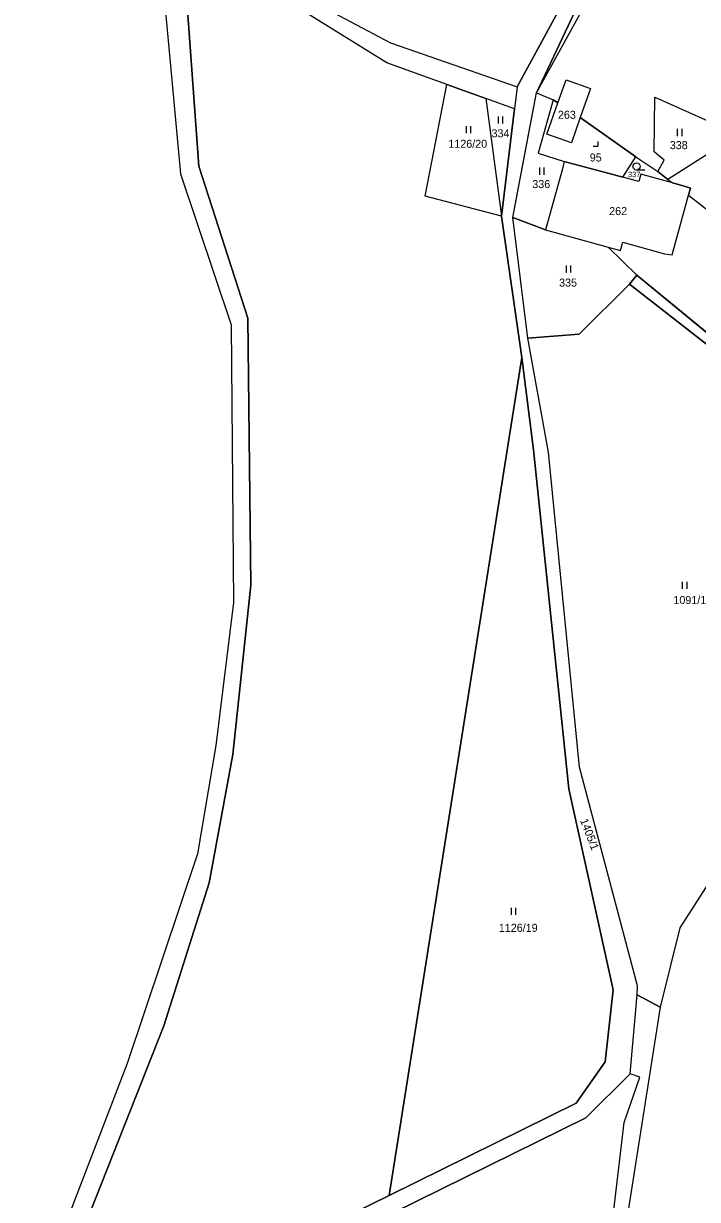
# Model space of a CAD drawing. Extents: x -588699 to -585793, y -1060280 to -1056731.
# Drawn here: x -587669 to -587526.4, y -1058613.5 to -1058364.5 of the extents above; entities that cross this region are included whole.
import ezdxf

# ---------------------------------------------------------------- set-up
doc = ezdxf.new("R2010")
doc.units = 0
for name, color, linetype in [('Druh pozemku', 7, 'Continuous'), ('Lesy', 7, 'Continuous'), ('Parcela nároku', 7, 'Continuous')]:
    doc.layers.add(name, color=color, linetype=linetype)

msp = doc.modelspace()

# ---------------------------------------------------------------- linework, layer by layer
at = {"layer": 'Druh pozemku'}
for p, q in [((-587568.6, -1058384.17), (-587568.6, -1058385.67)), ((-587567.58, -1058385.67), (-587567.58, -1058384.17)), ((-587575.35, -1058386.23), (-587575.35, -1058387.73)), ((-587574.33, -1058387.73), (-587574.33, -1058386.23)), ((-587530.66, -1058386.82), (-587530.66, -1058388.32)), ((-587529.64, -1058388.32), (-587529.64, -1058386.82)), ((-587559.82, -1058395.01), (-587559.82, -1058396.51)), ((-587558.8, -1058396.51), (-587558.8, -1058395.01)), ((-587537.52, -1058395.51), (-587539.27, -1058395.51)), ((-587554.19, -1058415.74), (-587554.19, -1058417.24)), ((-587553.17, -1058417.24), (-587553.17, -1058415.74)), ((-587529.59, -1058482.69), (-587529.59, -1058484.19)), ((-587528.57, -1058484.19), (-587528.57, -1058482.69)), ((-587565.84, -1058551.72), (-587565.84, -1058553.22)), ((-587564.82, -1058553.22), (-587564.82, -1058551.72))]:
    msp.add_line(p, q, dxfattribs=at)
msp.add_lwpolyline([(-587548.43, -1058390.48), (-587547.43, -1058390.48), (-587547.43, -1058389.48)], dxfattribs=at)
msp.add_circle((-587539.27, -1058394.76), 0.75, dxfattribs=at)
at = {"layer": 'Lesy'}
for p, q in [((-587560.48, -1058379.18), (-587539.23, -1058340.65)), ((-587565.45, -1058405.55), (-587560.48, -1058379.18)), ((-587562.32, -1058431.12), (-587565.45, -1058405.55)), ((-587539.18, -1058417.8), (-587540.79, -1058419.7)), ((-587518.94, -1058434.42), (-587539.18, -1058417.8)), ((-587540.79, -1058419.7), (-587551.44, -1058430.25)), ((-587551.44, -1058430.25), (-587562.32, -1058431.12))]:
    msp.add_line(p, q, dxfattribs=at)
at = {"layer": 'Parcela nároku'}
for points in [[(-587737.19, -1058617.25), (-587726.96, -1058577.41), (-587725.51, -1058469.33), (-587723.26, -1058358.68), (-587722.78, -1058330.1), (-587713.89, -1058330.1), (-587711.77, -1058326.33), (-587706.96, -1058322.08), (-587695.94, -1058320.38), (-587639.64, -1058348.59), (-587638.99, -1058362.02), (-587635.81, -1058396.35), (-587625.09, -1058428.31), (-587624.61, -1058487.07), (-587628.3, -1058517.38), (-587632.21, -1058540.26), (-587647.07, -1058584.65), (-587664.66, -1058630.41)], [(-587548.89, -1058349.03), (-587564.56, -1058377.91), (-587565.12, -1058382.56), (-587567.87, -1058405.29), (-587563.56, -1058435.22), (-587561.12, -1058454.74), (-587553.58, -1058526.52), (-587544.23, -1058569.1), (-587545.9, -1058584.35), (-587552.09, -1058593.05), (-587591.67, -1058612.59), (-587607.6, -1058620.46)], [(-587662.12, -1058634.33), (-587639.34, -1058576.72), (-587629.73, -1058546.44), (-587624.7, -1058519.28), (-587620.91, -1058483.41), (-587621.58, -1058426.86), (-587631.96, -1058394.68), (-587634.38, -1058360.7), (-587631.34, -1058352.01), (-587634.55, -1058350.69), (-587638.99, -1058362.02), (-587635.81, -1058396.35), (-587625.09, -1058428.31), (-587624.61, -1058487.07), (-587628.3, -1058517.38), (-587632.21, -1058540.26), (-587647.07, -1058584.65), (-587664.66, -1058630.41)], [(-587607.6, -1058620.46), (-587591.67, -1058612.59), (-587563.56, -1058435.22), (-587567.87, -1058405.29), (-587584.03, -1058401.03), (-587579.42, -1058377.42), (-587592.13, -1058372.84), (-587613.98, -1058359.18), (-587631.34, -1058352.01), (-587634.38, -1058360.7), (-587631.96, -1058394.68), (-587621.58, -1058426.86), (-587620.91, -1058483.41), (-587624.7, -1058519.28), (-587629.73, -1058546.44), (-587639.34, -1058576.72), (-587662.12, -1058634.33)], [(-587614.01, -1058356.52), (-587591.38, -1058368.57), (-587564.56, -1058377.91), (-587565.12, -1058382.56), (-587571.21, -1058380.37), (-587579.42, -1058377.42), (-587592.13, -1058372.84), (-587613.98, -1058359.18)], [(-587605.95, -1058623.77), (-587550, -1058596.19), (-587540.61, -1058586.85), (-587539.12, -1058570.16), (-587539.08, -1058568.25), (-587551.33, -1058521.95), (-587557.89, -1058455.23), (-587562.32, -1058431.12), (-587565.45, -1058405.55), (-587562.72, -1058391.01), (-587560.48, -1058379.18), (-587551.32, -1058359.88)], [(-587551.32, -1058359.88), (-587560.48, -1058379.18), (-587556.95, -1058380.65), (-587555.94, -1058381.31), (-587554.2, -1058376.4), (-587549.02, -1058378.23), (-587551.19, -1058384.39), (-587539.4, -1058392.75), (-587534.78, -1058395.8), (-587533.41, -1058393.41), (-587535.52, -1058391.66), (-587535.42, -1058380.1), (-587517.68, -1058388.02), (-587532.64, -1058397.54), (-587531.66, -1058398.23), (-587529.42, -1058398.84), (-587527.85, -1058399.33), (-587528.28, -1058400.85), (-587508.17, -1058416.49), (-587489.24, -1058400.75), (-587498.12, -1058378.59), (-587502.56, -1058362.06)]]:
    msp.add_lwpolyline(points, dxfattribs=at)
for points in [[(-587575.94, -1058326.51), (-587584.66, -1058324.18), (-587593.29, -1058321.73), (-587594.36, -1058321.43), (-587610.69, -1058335.67), (-587630.7, -1058349.56), (-587614.01, -1058356.52), (-587591.38, -1058368.57), (-587564.56, -1058377.91), (-587548.89, -1058349.03), (-587542.26, -1058338.73), (-587542.96, -1058338.45), (-587556.01, -1058332.97), (-587562.08, -1058330.38), (-587567.25, -1058328.93)], [(-587555.94, -1058381.31), (-587554.2, -1058376.4), (-587549.02, -1058378.23), (-587551.19, -1058384.39), (-587553.07, -1058389.74), (-587558.27, -1058387.9)], [(-587584.03, -1058401.03), (-587579.42, -1058377.42), (-587571.21, -1058380.37), (-587567.87, -1058405.29)], [(-587560.13, -1058391.95), (-587554.61, -1058393.67), (-587554.98, -1058395.27), (-587558.05, -1058406.42), (-587558.54, -1058408.19), (-587565.45, -1058405.55), (-587562.72, -1058391.01), (-587560.48, -1058379.18), (-587556.95, -1058380.65)], [(-587565.12, -1058382.56), (-587571.21, -1058380.37), (-587567.87, -1058405.29)], [(-587556.95, -1058380.65), (-587560.13, -1058391.95), (-587554.61, -1058393.67), (-587542.18, -1058397.01), (-587539.4, -1058392.75), (-587551.19, -1058384.39), (-587553.07, -1058389.74), (-587558.27, -1058387.9), (-587555.94, -1058381.31)], [(-587535.52, -1058391.66), (-587535.42, -1058380.1), (-587517.68, -1058388.02), (-587532.64, -1058397.54), (-587534.78, -1058395.8), (-587533.41, -1058393.41)], [(-587554.98, -1058395.27), (-587558.05, -1058406.42), (-587558.54, -1058408.19), (-587545.3, -1058411.83), (-587542.65, -1058412.55), (-587542.17, -1058410.8), (-587533.38, -1058413.22), (-587531.76, -1058413.48), (-587528.28, -1058400.85), (-587527.85, -1058399.33), (-587529.42, -1058398.84), (-587531.66, -1058398.23), (-587538.37, -1058396.38), (-587538.79, -1058397.92), (-587542.18, -1058397.01), (-587554.61, -1058393.67)], [(-587532.64, -1058397.54), (-587531.66, -1058398.23), (-587538.37, -1058396.38), (-587538.79, -1058397.92), (-587542.18, -1058397.01), (-587539.4, -1058392.75), (-587534.78, -1058395.8)], [(-587508.17, -1058416.49), (-587483.73, -1058440.23), (-587487.34, -1058444.4), (-587493.32, -1058457.45), (-587518.94, -1058434.42), (-587539.18, -1058417.8), (-587545.3, -1058411.83), (-587542.65, -1058412.55), (-587542.17, -1058410.8), (-587533.38, -1058413.22), (-587531.76, -1058413.48), (-587528.28, -1058400.85)], [(-587565.45, -1058405.55), (-587558.54, -1058408.19), (-587545.3, -1058411.83), (-587539.18, -1058417.8), (-587540.79, -1058419.7), (-587551.44, -1058430.25), (-587562.32, -1058431.12)], [(-587540.79, -1058419.7), (-587539.18, -1058417.8), (-587518.94, -1058434.42), (-587493.32, -1058457.45), (-587494.4, -1058459.8), (-587520.3, -1058435.59)], [(-587551.44, -1058430.25), (-587540.79, -1058419.7), (-587520.3, -1058435.59), (-587494.4, -1058459.8), (-587493.32, -1058457.45), (-587489.24, -1058461.4), (-587499.82, -1058493.7), (-587511.09, -1058507.48), (-587517.95, -1058537.05), (-587530.13, -1058555.98), (-587534.28, -1058572.77), (-587539.12, -1058570.16), (-587539.08, -1058568.25), (-587551.33, -1058521.95), (-587557.89, -1058455.23), (-587562.32, -1058431.12)], [(-587561.12, -1058454.74), (-587563.56, -1058435.22), (-587591.67, -1058612.59), (-587552.09, -1058593.05), (-587545.9, -1058584.35), (-587544.23, -1058569.1), (-587553.58, -1058526.52)], [(-587482.27, -1058467.36), (-587489.24, -1058461.4), (-587499.82, -1058493.7), (-587511.09, -1058507.48), (-587517.95, -1058537.05), (-587530.13, -1058555.98), (-587534.28, -1058572.77), (-587541.81, -1058620.72), (-587547.27, -1058648.34), (-587545.21, -1058649.21), (-587523.16, -1058658.51), (-587519.89, -1058645.26), (-587503.55, -1058608.11), (-587483.06, -1058578.42), (-587446.36, -1058525.22)], [(-587539.12, -1058570.16), (-587534.28, -1058572.77), (-587541.81, -1058620.72), (-587547.27, -1058648.34), (-587552.28, -1058648.34), (-587544.06, -1058615.74), (-587541.88, -1058597.15), (-587538.61, -1058587.55), (-587540.61, -1058586.85)], [(-587555.44, -1058720.83), (-587567.98, -1058710.91), (-587568.51, -1058703.4), (-587557.67, -1058698.35), (-587557.12, -1058684.85), (-587563.12, -1058678.39), (-587554.81, -1058665.52), (-587552.28, -1058648.34), (-587544.06, -1058615.74), (-587541.88, -1058597.15), (-587538.61, -1058587.55), (-587540.61, -1058586.85), (-587550, -1058596.19), (-587605.95, -1058623.77), (-587611.6, -1058632.08), (-587635.03, -1058707.54), (-587651.11, -1058765.46), (-587661.81, -1058786.25), (-587575.09, -1058769.86), (-587567.46, -1058768.42), (-587557.48, -1058747.69), (-587549.47, -1058725.55)]]:
    msp.add_lwpolyline(points, close=True, dxfattribs=at)

# ---------------------------------------------------------------- texts
for s, height, p in [('263', 1.7, (-587555.92, -1058384.66)), ('334', 1.7, (-587569.97, -1058388.59)), ('1126/20', 1.7, (-587579.11, -1058390.8)), ('338', 1.7, (-587532.24, -1058391.09)), ('95', 1.7, (-587549.18, -1058393.7)), ('337', 1.14, (-587541.09, -1058397.02)), ('336', 1.7, (-587561.34, -1058399.34)), ('262', 1.7, (-587545.07, -1058405.05)), ('335', 1.7, (-587555.67, -1058420.19)), ('1091/1', 1.7, (-587531.47, -1058487.4)), ('1126/19', 1.7, (-587568.43, -1058556.8))]:
    msp.add_text(s, height=height, dxfattribs=at).set_placement(p)
msp.add_text('1405/1', height=1.7, rotation=291.1839, dxfattribs=at).set_placement((-587551.26, -1058533.2))

doc.saveas('drawing.dxf')
